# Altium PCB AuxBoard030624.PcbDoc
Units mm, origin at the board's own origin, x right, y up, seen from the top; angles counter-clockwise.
Board outline 193.93 x 90.42 mm, 2 copper layers (Top Layer, Bottom Layer); 177 components, 141 nets, 489 pads, 90 vias.
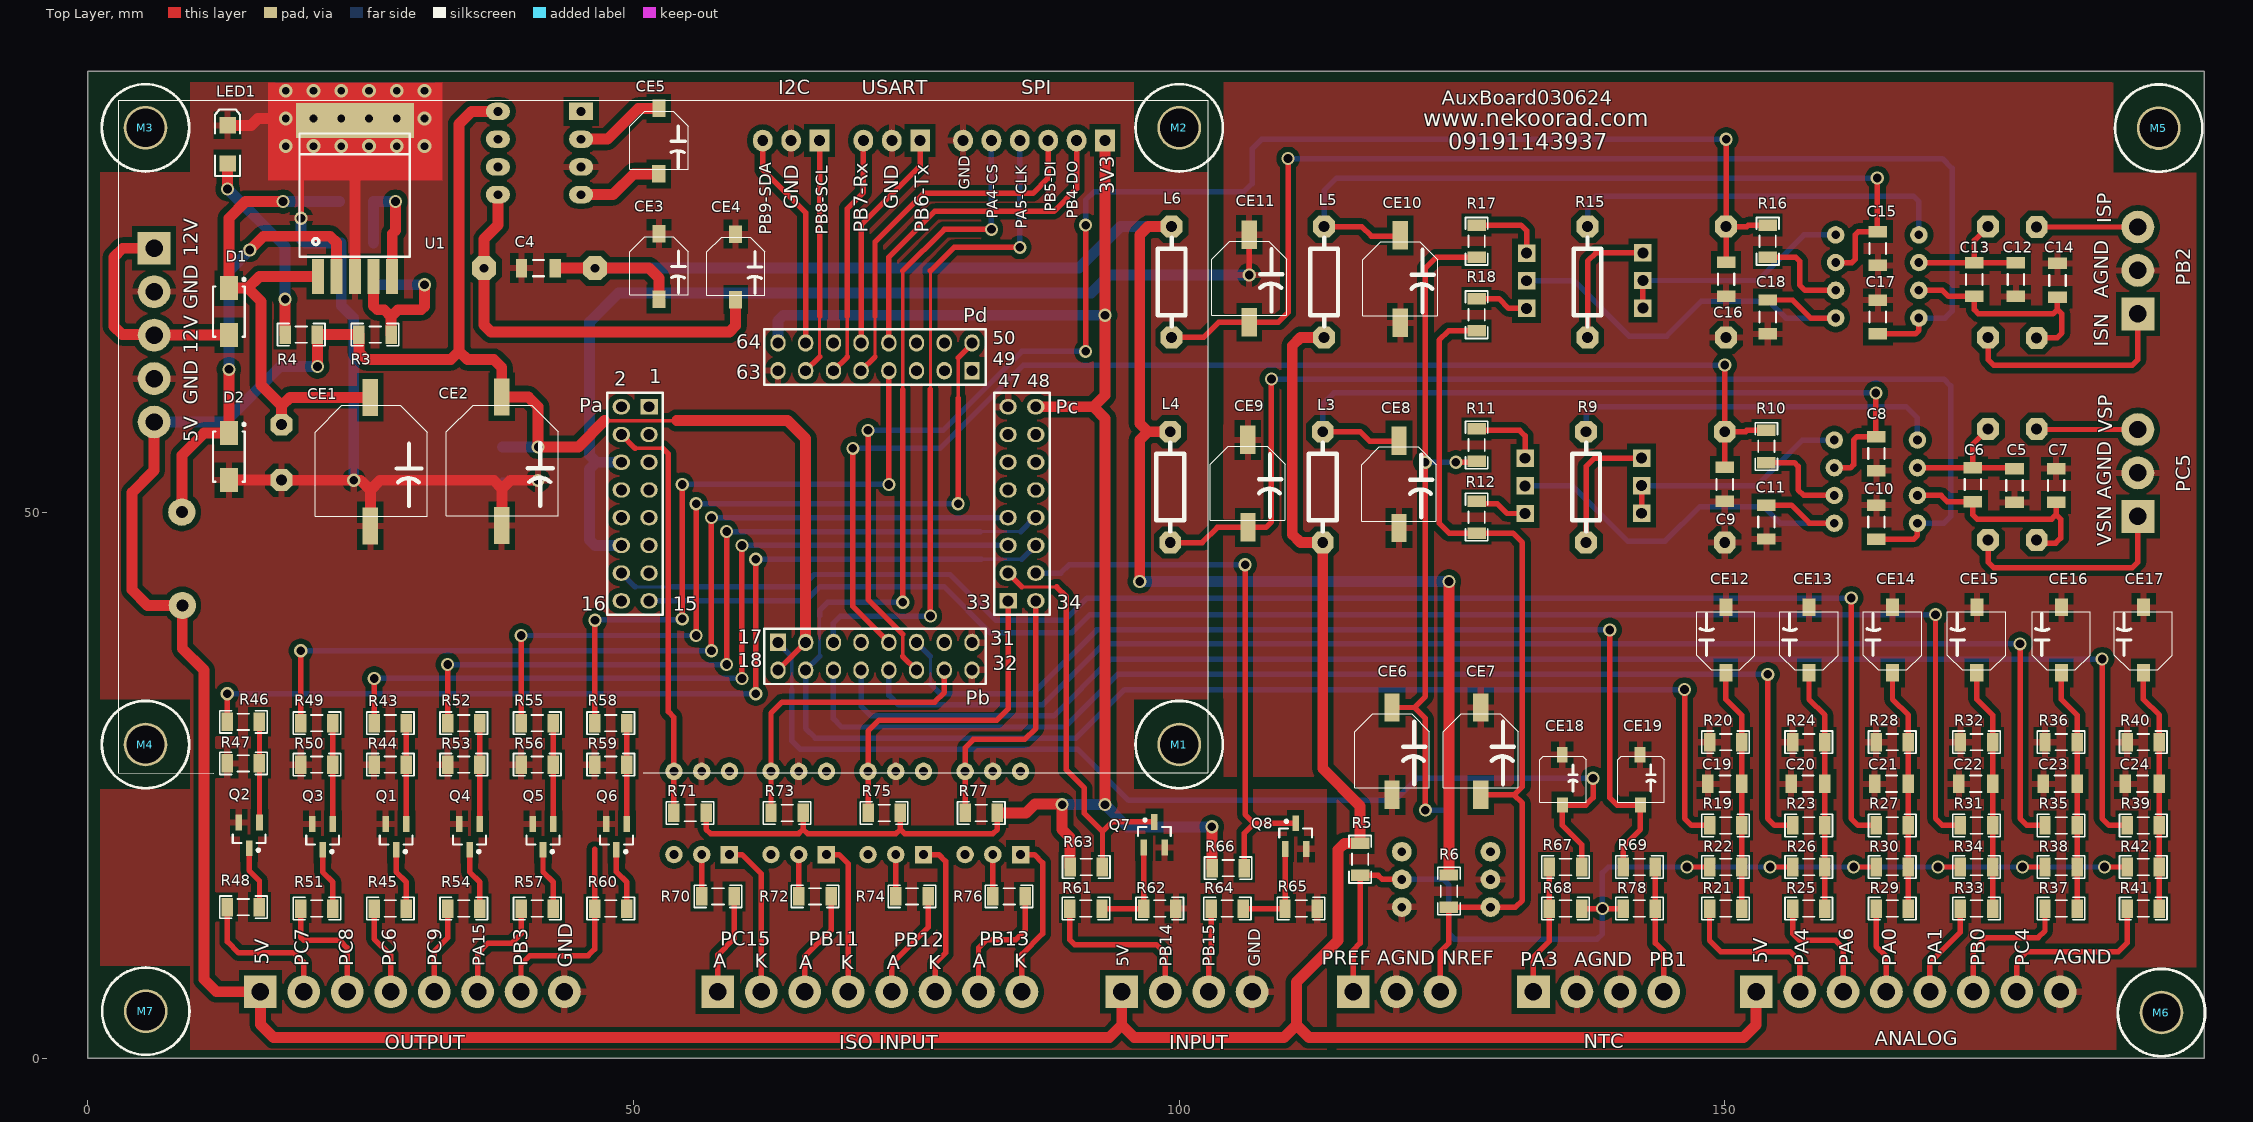
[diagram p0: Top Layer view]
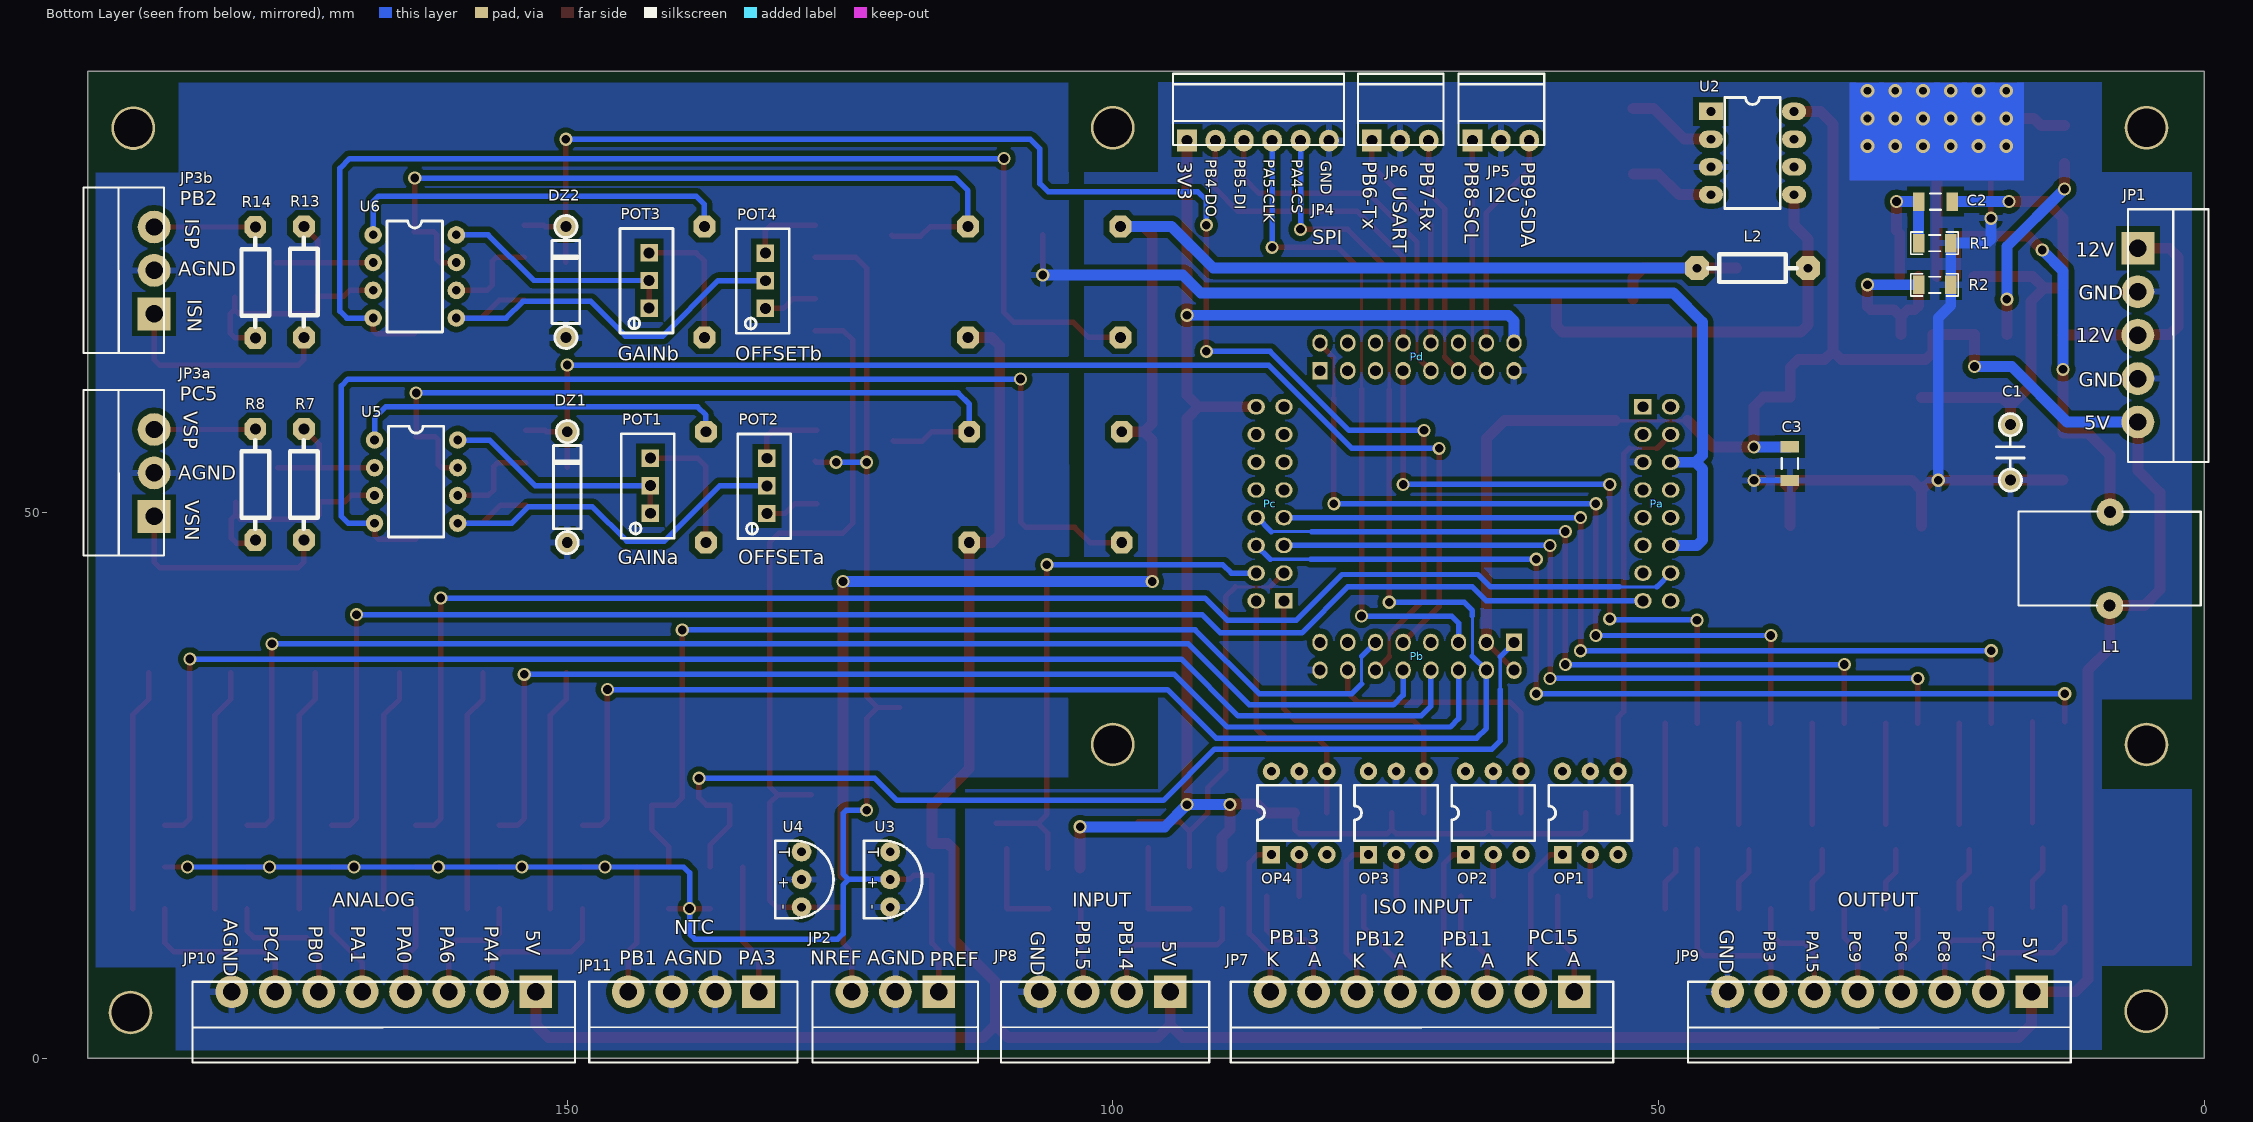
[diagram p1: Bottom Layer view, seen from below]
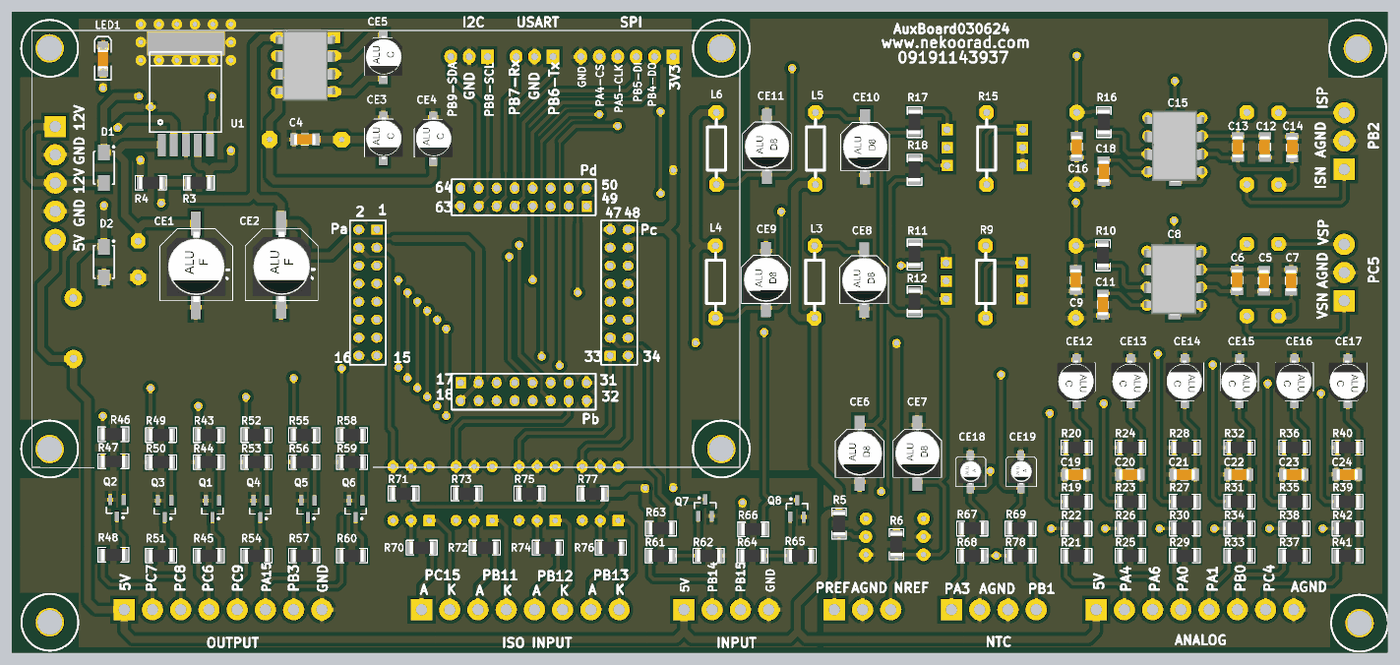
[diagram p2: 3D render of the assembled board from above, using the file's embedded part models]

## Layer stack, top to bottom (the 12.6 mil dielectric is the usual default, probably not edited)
Top Solder: solder mask 0.0102, Solder Resist, Dk 3.5
Top Layer: signal copper 0.0356
Dielectric 1: dielectric 0.32, FR-4, Dk 4.8
Bottom Layer: signal copper 0.0356
Bottom Solder: solder mask 0.0102, Solder Resist, Dk 3.5

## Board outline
0,0 0,90.424 193.929,90.424 193.929,0

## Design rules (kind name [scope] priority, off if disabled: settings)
Clearance Poly [All vs InPolygon] p1: gap=0.5 ignorepadtopadclearanceinfootprint=FALSE
Clearance [All] p2: gap=0.4 ignorepadtopadclearanceinfootprint=FALSE
PlaneClearance [All] p1: clearance=0.5
PlaneConnect [All] p1: planeconnectstyle=Relief reliefexpansion=0.508 reliefentries=4 reliefconductorwidth=0.6 reliefairgap=0.5
PolygonConnect [All] p1: connectstyle=Relief reliefconductorwidth=0.6 reliefentries=4 polygonreliefangle="90 Angle" airgapwidth=0.5
RoutingVias [All] p1: holewidth=0.711 width=1.27 viastyle="Through Hole" minholewidth=0.711 minwidth=1.27 maxholewidth=0.711 maxwidth=1.27
SolderMaskExpansion [All] p1: expansion=0.102 istentingtop=FALSE
Width [All] p1: maxlimit=1 minlimit=0.2 preferedwidth=0.5 minimp=50.000000 maximp=50.000000 favimp=50.000000
28 further rules are at their usual default settings.

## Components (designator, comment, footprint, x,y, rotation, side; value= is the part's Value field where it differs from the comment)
C1 "100N" C2P 17.78,58.048 r270 bottom
C2 "100N" SMD_CAP_1206. 24.642,78.486 r0 bottom
C3 "100N" SMD_CAP_1206. 37.973,54.483 r270 bottom
C4 "100N" SMD_CAP_1206. 41.3,72.39 r180 top
C5 "1N" SMD_CAP_1206. 176.53,52.476 r270 top
C6 "10N" SMD_CAP_1206. 172.72,52.553 r270 top
C7 "1N" SMD_CAP_1206. 180.34,52.476 r90 top
C8 "100N" SMD_CAP_1206. 163.883,55.396 r90 top
C9 "100N" SMD_CAP_1206. 149.987,52.578 r270 top
C10 "100N" SMD_CAP_1206. 163.883,49.122 r90 top
C11 "100N" SMD_CAP_1206. 153.797,49.124 r270 top
C12 "1N" SMD_CAP_1206. 176.657,71.349 r270 top
C13 "10N" SMD_CAP_1206. 172.847,71.349 r270 top
C14 "1N" SMD_CAP_1206. 180.467,71.272 r90 top
C15 "100N" SMD_CAP_1206. 164.01,74.192 r90 top
C16 "100N" SMD_CAP_1206. 150.114,71.374 r270 top
C17 "100N" SMD_CAP_1206. 164.01,67.918 r90 top
C18 "100N" SMD_CAP_1206. 153.924,67.92 r270 top
C19 "ND" SMD_CAP_1206. 149.991,25.146 r180 top
C20 "ND" SMD_CAP_1206. 157.611,25.146 r180 top
C21 "ND" SMD_CAP_1206. 165.26,25.146 r180 top
C22 "ND" SMD_CAP_1206. 172.978,25.146 r180 top
C23 "ND" SMD_CAP_1206. 180.725,25.146 r180 top
C24 "ND" SMD_CAP_1206. 188.247,25.146 r180 top
CE1 "470M/25" CAP-E-6 26.068,51.018 r0 top
CE2 "1000M/16" CAP-E-6 38.1,51.054 r0 top
CE3 "10M/25" CAP-E-3 52.414,70.651 r0 top
CE4 "10M/25" CAP-E-3 59.436,70.612 r0 top
CE5 "10M/25" CAP-E-3 52.399,82.126 r0 top
CE6 "47M" CAP-E-4 119.507,25.84 r0 top
CE7 "47M" CAP-E-4 127.635,25.84 r0 top
CE8 "47M" CAP-E-4 120.142,50.292 r0 top
CE9 "47M" CAP-E-4 106.299,50.351 r0 top
CE10 "47M" CAP-E-4 120.269,69.088 r0 top
CE11 "47M" CAP-E-4 106.426,69.147 r0 top
CE12 "ND" CAP-E-3 150.02,40.206 r180 top
CE13 "ND" CAP-E-3 157.64,40.206 r180 top
CE14 "ND" CAP-E-3 165.289,40.206 r180 top
CE15 "ND" CAP-E-3 173.007,40.206 r180 top
CE16 "ND" CAP-E-3 180.754,40.206 r180 top
CE17 "ND" CAP-E-3 188.276,40.206 r180 top
CE18 "1M" CAP-E-2 135.189,24.423 r0 top
CE19 "1M" CAP-E-2 142.33,24.423 r0 top
D1 "schottky" SMA-M 12.954,68.403 r270 top
D2 "schottky" SMA-M 12.954,55.118 r270 top
DZ1 "3V" D4P 149.987,47.244 r270 bottom
DZ2 "3V" D4P 150.114,66.04 r270 bottom
JP1 "DC_SUP" "dsip 5 right" 6.096,66.253 r180 bottom
JP2 "Ref" "dsip 3 right" 123.952,6.096 r270 bottom
JP3a "V/A Signal" "dsip 3 right" 187.833,57.658 r0 bottom
JP3b "V/A Signal" "dsip 3 right" 187.833,76.21 r0 bottom
JP4 "SPI" "SIP 6 Right" 93.204,84.074 r270 bottom
JP5 "I2C" "SIP 3 Right" 67.107,83.947 r270 bottom
JP6 "UART" "SIP 3 Right" 76.327,83.947 r270 bottom
JP7 "ISO DIN" "dsip 8 right" 57.763,6.071 r270 bottom
JP8 "DIN" "dsip 4 right" 102.727,6.096 r270 bottom
JP9 "DOUT" "dsip 8 right" 15.853,6.071 r270 bottom
JP10 "Analog" "dsip 8 right" 152.886,6.071 r270 bottom
JP11 "NTC" "dsip 4 right" 140.444,6.096 r270 bottom
L1 "100UH" INDUCTOR-ylw 0.401,49.893 r0 bottom
L2 "100UH" r4p#1 36.322,72.39 r270 bottom
L3 "100UH" r4p#2 113.157,47.244 r180 top
L4 "100UH" r4p#2 99.187,57.404 r0 top
L5 "100UH" r4p#2 113.284,66.04 r180 top
L6 "100UH" r4p#2 99.314,76.2 r0 top
LED1 "Red" LED_SMD_1206 15.048,83.815 r90 top
M1 "Comment" Stud-hole 100.006,28.745 r0 top locked value=DNP/MH
M2 "Comment" Stud-hole 100.006,85.245 r0 top locked value=DNP/MH
M3 "Comment" Stud-hole 5.306,85.245 r0 top locked value=DNP/MH
M4 "Comment" Stud-hole 5.306,28.745 r0 top locked value=DNP/MH
M5 "Comment" Stud-hole 189.738,85.217 r0 top value=DNP/MH
M6 "Comment" Stud-hole 189.992,4.191 r0 top value=DNP/MH
M7 "Comment" Stud-hole 5.334,4.318 r0 top value=DNP/MH
OP1 "4N28" DIP6 58.801,18.669 r90 bottom
OP2 "4N28" DIP6 67.691,18.669 r90 bottom
OP3 "4N28" DIP6 76.581,18.669 r90 bottom
OP4 "4N28" DIP6 85.471,18.669 r90 bottom
Pa "Header 8X2" HDR2X8#1 51.435,59.69 r270 bottom locked
Pb "Header 8X2" HDR2X8#2 63.246,38.1 r0 bottom locked
Pc "Header 8X2" HDR2X8#1 84.328,41.91 r90 bottom locked
Pd "Header 8X2" HDR2X8#1 81.026,62.992 r180 bottom locked
POT1 "ND" "pot multi turn" 142.367,49.931 r180 bottom
POT2 "ND" "pot multi turn" 131.699,49.911 r180 bottom
POT3 "ND" "pot multi turn" 142.494,68.727 r180 bottom
POT4 "ND" "pot multi turn" 131.826,68.707 r180 bottom
Q1 "2N2222" 2N2222 28.36,21.988 r180 top
Q2 "2N2222" 2N2222 14.898,22.115 r180 top
Q3 "2N2222" 2N2222 21.629,21.988 r180 top
Q4 "2N2222" 2N2222 35.091,21.988 r180 top
Q5 "2N2222" 2N2222 41.822,21.988 r180 top
Q6 "2N2222" 2N2222 48.553,21.988 r180 top
Q7 "2N2222" 2N2222 97.624,18.779 r0 top
Q8 "2N2222" 2N2222 110.578,18.652 r0 top
R1 "10K%" RES_1206 24.68,73.795 r180 bottom
R2 "2K2%" RES_1206 24.68,69.985 r180 bottom
R3 "47K%" RES_1206 26.374,65.413 r0 top
R4 "4K7%" RES_1206 19.542,67.175 r180 top
R5 "270R" RES_1206 117.467,18.275 r90 top
R6 "270R" RES_1206 125.595,15.354 r90 top
R7 "10K%" R4P 174.117,47.498 r0 bottom
R8 "10K%" R4P 178.562,57.658 r180 bottom
R9 "ND" R4P 137.287,57.404 r0 top
R10 "1K%" RES_1206 152.916,56.02 r270 top
R11 "ND" RES_1206 128.135,56.219 r90 top
R12 "ND" RES_1206 126.373,49.543 r270 top
R13 "10K%" R4P 174.117,66.04 r0 bottom
R14 "10K%" R4P 178.562,76.159 r180 bottom
R15 "ND" R4P 137.414,76.2 r0 top
R16 "1K%" RES_1206 153.043,74.816 r270 top
R17 "ND" RES_1206 128.135,74.888 r90 top
R18 "ND" RES_1206 126.373,68.085 r270 top
R19 "1K%" RES_1206 150.101,20.455 r0 top
R20 "ND" RES_1206 150.101,28.075 r0 top
R21 "ND" RES_1206 150.029,14.597 r180 top
R22 "ND" RES_1206 150.101,16.645 r0 top
R23 "1K%" RES_1206 157.721,20.455 r0 top
R24 "ND" RES_1206 157.721,28.075 r0 top
R25 "ND" RES_1206 157.649,14.597 r180 top
R26 "ND" RES_1206 157.721,16.645 r0 top
R27 "1K%" RES_1206 165.37,20.455 r0 top
R28 "ND" RES_1206 165.37,28.075 r0 top
R29 "ND" RES_1206 165.298,14.597 r180 top
R30 "ND" RES_1206 165.37,16.645 r0 top
R31 "1K%" RES_1206 173.088,20.455 r0 top
R32 "ND" RES_1206 173.088,28.075 r0 top
R33 "ND" RES_1206 173.016,14.597 r180 top
R34 "ND" RES_1206 173.088,16.645 r0 top
R35 "1K%" RES_1206 180.835,20.455 r0 top
R36 "ND" RES_1206 180.835,28.075 r0 top
R37 "ND" RES_1206 180.763,14.597 r180 top
R38 "ND" RES_1206 180.835,16.645 r0 top
R39 "1K%" RES_1206 188.357,20.455 r0 top
R40 "ND" RES_1206 188.357,28.075 r0 top
R41 "ND" RES_1206 188.285,14.597 r180 top
R42 "ND" RES_1206 188.357,16.645 r0 top
R43 "4K7" RES_1206 27.771,29.824 r0 top
R44 "2K2" RES_1206 27.699,27.776 r180 top
R45 "ND" RES_1206 27.699,14.597 r180 top
R46 "4K7" RES_1206 14.309,29.951 r0 top
R47 "2K2" RES_1206 14.237,27.903 r180 top
R48 "ND" RES_1206 14.237,14.724 r180 top
R49 "4K7" RES_1206 21.04,29.824 r0 top
R50 "2K2" RES_1206 20.968,27.776 r180 top
R51 "ND" RES_1206 20.968,14.597 r180 top
R52 "4K7" RES_1206 34.502,29.824 r0 top
R53 "2K2" RES_1206 34.43,27.776 r180 top
R54 "ND" RES_1206 34.43,14.597 r180 top
R55 "4K7" RES_1206 41.233,29.824 r0 top
R56 "2K2" RES_1206 41.161,27.776 r180 top
R57 "ND" RES_1206 41.161,14.597 r180 top
R58 "4K7" RES_1206 47.964,29.824 r0 top
R59 "2K2" RES_1206 47.892,27.776 r180 top
R60 "ND" RES_1206 47.892,14.597 r180 top
R61 "10K" RES_1206 91.496,12.835 r0 top
R62 "4K7" RES_1206 98.256,12.835 r0 top
R63 "10K" RES_1206 91.525,16.645 r0 top
R64 "10K" RES_1206 104.45,12.835 r0 top
R65 "4K7" RES_1206 111.21,12.835 r0 top
R66 "10K" RES_1206 104.529,16.532 r0 top
R67 "10K" RES_1206 135.438,16.645 r0 top
R68 "5K" RES_1206 135.366,14.597 r180 top
R69 "10K" RES_1206 142.126,18.407 r180 top
R70 "1K%" RES_1206 57.714,15.726 r180 top
R71 "10K%" RES_1206 55.232,21.598 r0 top
R72 "1K%" RES_1206 66.604,15.726 r180 top
R73 "10K%" RES_1206 64.122,21.598 r0 top
R74 "1K%" RES_1206 75.494,15.726 r180 top
R75 "10K%" RES_1206 73.012,21.598 r0 top
R76 "1K%" RES_1206 84.384,15.726 r180 top
R77 "10K%" RES_1206 81.902,21.598 r0 top
R78 "5K" RES_1206 142.198,12.835 r0 top
U1 "LM2576T-ADJ" D2PACK_TO263-5 24.511,76.327 r0 top
U2 "ICL7662" DIP8#1 45.212,86.741 r180 bottom
U3 "LM336-2V5" lm336 120.396,13.843 r180 bottom
U4 "LM336-2V5" lm336 128.524,13.843 r180 bottom
U5 "AD620" DIP8#2 167.64,56.642 r180 bottom
U6 "AD620" DIP8#2 167.767,75.438 r180 bottom

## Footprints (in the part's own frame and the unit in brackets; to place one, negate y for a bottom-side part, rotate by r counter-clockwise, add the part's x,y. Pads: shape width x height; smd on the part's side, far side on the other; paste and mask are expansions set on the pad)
2N2222 [mm] "SOT_23"
  rect 0.6x1.45 smd: 1(-0.85,0.525) 2(1.05,0.525) 3(0.1,2.875)
  silkscreen extent -1.4,1.6 1.6,3.17, body extent -1.4,1 1.6,2.4, height 1.1
C2P [mm]
  oct 2x2 hole 1: 1(0,0) 2(5.08,0)
  silkscreen extent -1.02,-1.27 6.1,1.27
CAP-E-2 [mm] "1u-50v"
  rect 1x1.4 smd: 1(-0.09,3.39) 2(-0.075,-1.22)
  silkscreen extent -2.17,-0.98 2.11,3.25, body extent -1.68,-0.65 1.62,2.95, height 5.4
CAP-E-3 [mm] "22u-35v"
  rect 1.2x1.6 smd: 1(-0.065,4.9) 2(-0.075,-1.1)
  silkscreen extent -2.72,-0.69 2.62,4.62, body extent -2.64,-1.03 2.66,4.87, height 5.41
CAP-E-4 [mm] "(100u-35v)(47u-16v)(220u-16v)(100u-16v)(10u-50v)"
  rect 1.4x2.6 smd: 1(-0.005,6.3) 2(0,-1.71)
  silkscreen extent -3.43,-1.07 3.43,5.71, body extent -3.27,-1.22 3.33,5.78, height 7.7
CAP-E-6 [mm] "(220u-35v)(470u-25v)"
  rect 1.4x3.4 smd: 1(-0.16,9.535) 2(-0.16,-2.25)
  silkscreen extent -5.22,-1.35 5.03,8.79, body extent -4.24,-1.54 4.06,8.36, height 10.2
D2PACK_TO263-5 [mm]
  rect 1.1x3.2 smd: 1(-3.4,-4.7) 2(-1.7,-4.7) 3(0,-4.7) 4(1.7,-4.7) 5(3.4,-4.7)
  rect 10.8x3.2 smd: 3(0,9.6)
  silkscreen extent -5.1,-2.9 5,8.4, body extent -5.1,-4.62 5.06,9.62, height 4.87
D4P [mm]
  oct 2x2 hole 1: 1(0,0) 2(-10.16,0)
  silkscreen extent -11.18,-1.27 1.02,1.27
DIP6 [mm]
  rect 1.6x1.6 hole 0.8: 1(0,0)
  round 1.6 hole 0.8: 2(0,-2.54) 3(0,-5.08) 4(7.62,-5.08) 5(7.62,-2.54) 6(7.62,0)
  silkscreen extent 1.27,-6.35 6.35,1.27
DIP8#1 [mm]
  rect 2.2x1.6 hole 0.8: 1(0,0)
  oval 2.2x1.6 hole 0.8: 2(0,-2.54) 3(0,-5.08) 4(0,-7.62) 5(7.62,-7.62) 6(7.62,-5.08) 7(7.62,-2.54) 8(7.62,0)
  silkscreen extent 1.27,-8.89 6.35,1.27, body extent -1.42,-8.88 9.14,1.02, height 3.75
DIP8#2 [mm]
  round 1.6 hole 0.8: 1(0,0) 2(0,-2.54) 3(0,-5.08) 4(0,-7.62) 5(7.62,-7.62) 6(7.62,-5.08) 7(7.62,-2.54) 8(7.62,0)
  silkscreen extent 1.27,-8.89 6.35,1.27, body extent -1.42,-8.88 9.14,1.02, height 3.75
"dsip 3 right" [mm]
  rect 3x3 hole 1.6: 1(0,8.011)
  round 3 hole 1.6: 2(0,4.031) 3(0,0.051)
  silkscreen extent -0.91,-3.56 6.48,11.59
"dsip 4 right" [mm]
  rect 3x3 hole 1.6: 1(0,7.985)
  round 3 hole 1.6: 2(0,4.005) 3(0,0.025) 4(0,-3.955)
  silkscreen extent -0.91,-7.52 6.48,11.56
"dsip 5 right" [mm]
  rect 3x3 hole 1.6: 1(0,7.96)
  round 3 hole 1.6: 2(0,3.98) 3(0,0) 4(0,-3.98) 5(0,-7.96)
  silkscreen extent -0.91,-11.63 6.48,11.53
"dsip 8 right" [mm]
  rect 3x3 hole 1.6: 1(-0.025,0.025)
  round 3 hole 1.6: 2(-0.025,-3.955) 3(-0.025,-7.935) 4(-0.025,-11.915) 5(-0.025,-15.895) 6(-0.025,-19.875) 7(-0.025,-23.855) 8(-0.025,-27.835)
  silkscreen extent -0.94,-31.45 6.45,3.6
HDR2X8#1 [mm] "Connector; Header; 8x2 Position"
  rect 1.4x1.6 hole 1: 1(0,0)
  oval 1.4x1.6 hole 1: 2(0,2.54) 3(2.54,0) 4(2.54,2.54) 5(5.08,0) 6(5.08,2.54) 7(7.62,0) 8(7.62,2.54) 9(10.16,0) 10(10.16,2.54) 11(12.7,0) 12(12.7,2.54) 13(15.24,0) 14(15.24,2.54) 15(17.78,0) 16(17.78,2.54)
HDR2X8#2 [mm] "Connector; Header; 8x2 Position"
  rect 1.5x1.6 hole 1: 1(0,0)
  oval 1.4x1.6 hole 1: 2(0,2.54) 3(2.54,0) 4(2.54,2.54) 5(5.08,0) 6(5.08,2.54) 7(7.62,0) 8(7.62,2.54) 9(10.16,0) 10(10.16,2.54) 11(12.7,0) 12(12.7,2.54) 13(15.24,0) 14(15.24,2.54) 15(17.78,0) 16(17.78,2.54)
INDUCTOR-ylw [mm]
  round 2.5 hole 1.1: 1(8.275,8.405) 2(8.235,-0.145)
  silkscreen extent -0.07,-0.21 16.63,8.42
LED_SMD_1206 [mm] "SMD"
  rect 1.5x1.5 smd: 1(-1.844,2.221) 2(1.656,2.221)
  silkscreen extent -2.99,1.07 3.11,3.37, body extent -1.74,1.46 1.56,2.91, height 1.36
lm336 [mm]
  round 1.8 hole 0.8: 1(0,0) 2(0,2.54) 3(0,5.08)
  silkscreen extent -2.41,-1.02 2.92,6.1
"pot multi turn" [mm]
  rect 1.6x1.6 hole 1: 1(0,5.06) 2(0,0) 3(0,2.53)
  silkscreen extent -2.67,-2.29 2.18,7.29
r4p#1 [mm]
  oct 2.2x2.2 hole 0.8: 1(0,0) 2(0,-10.16)
  silkscreen extent -1.27,-9.14 1.27,-1.02
r4p#2 [mm]
  oct 2x2 hole 1: 1(0,0) 2(0,-10.16)
  silkscreen extent -1.27,-9.14 1.27,-1.02
R4P [mm]
  oct 2x2 hole 1: 1(0,0) 2(0,-10.16)
  silkscreen extent -1.27,-9.14 1.27,-1.02
RES_1206 [mm] "SMD"
  rect 1.05x1.7 smd: 1(-1.511,0.881) 2(1.439,0.881)
  silkscreen extent -2.21,-0.14 2.14,1.91, body extent -1.69,0.03 1.61,1.73, height 0.94
"SIP 3 Right" [mm]
  rect 2x1.8 hole 1: 1(-0.127,0.051)
  oval 2x1.8 hole 1: 2(-0.127,2.651) 3(-0.127,5.251)
  silkscreen extent -6.25,-1.22 0.28,6.63
"SIP 6 Right" [mm]
  rect 2x1.8 hole 1: 1(0,0)
  oval 2x1.8 hole 1: 2(0,2.6) 3(0,5.2) 4(0,7.8) 5(0,10.4) 6(0,13)
  silkscreen extent -6.12,-1.3 0.41,14.38
SMA-M [mm] "Molded Diode, 2-Leads, Body 4.30x2.70mm, IPC Low Density"
  rect 2.2x1.65 smd: 1(2.15,0) 2(-2.15,0)
  silkscreen extent -3.07,-1.45 2.3,1.5, body extent -2.3,-1.45 2.3,1.45, height 2.44
SMD_CAP_1206. [mm]
  rect 1.05x1.7 smd: 1(-1.549,0) 2(1.549,0)
  silkscreen extent -0.5,-0.75 0.5,0.75, body extent -1.52,-0.77 1.53,0.75, height 0.75
Stud-hole [mm]
  round 4 hole 3.5: 1(0,0)
  silkscreen extent -4,-4 4,4

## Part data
C1 C2 C3 C4 C5 C6 C7 C8 C9 C10 C11 C12 C13 C14 C15 C16 C17 C18 C19 C20 C21 C22 C23 C24: library part C
CE1 CE2 CE3 CE4 CE5 CE6 CE7 CE8 CE9 CE10 CE11 CE12 CE13 CE14 CE15 CE16 CE17 CE18 CE19: library part E
D1 D2: library part Diode, "Default Diode"
DZ1 DZ2: library part Z
JP1: library part "HEADER 5"
JP2 JP3a JP3b JP5 JP6: library part "Header 3", "Header, 3-Pin"
JP4: library part "HEADER 6"
JP7 JP9 JP10: library part "HEADER 8"
JP8 JP11: library part "Header 4", "Header, 4-Pin"
L1 L2 L3 L4 L5 L6: library part "INDUCTOR IRON"
LED1: library part LED, "LED"
M1 M2 M3 M4 M5 M6 M7: library part SCMH_M1P6, "SCREW mouting, M1.6, 1.6mm diameter and 3.2mm PanHead"
OP1 OP2 OP3 OP4: library part OPTODIP6
Pa Pb Pc Pd: "Header, 8-Pin, Dual row"
POT1 POT2 POT3 POT4: library part POT2
Q1 Q2 Q3 Q4 Q5 Q6 Q7 Q8: library part 1FW, "NPN"
R1 R2 R3 R4 R5 R6 R7 R8 R9 R10 R11 R12 R13 R14 R15 R16 R17 R18 R19 R20 R21 R22 R23 R24 R25 R26 R27 R28 R29 R30 R31 R32 R33 R34 R35 R36 R37 R38 R39 R40 R41 R42 R43 R44 R45 R46 R47 R48 R49 R50 R51 R52 R53 R54 R55 R56 R57 R58 R59 R60 R61 R62 R63 R64 R65 R66 R67 R68 R69 R70 R71 R72 R73 R74 R75 R76 R77 R78: library part R
U1: library part LM2576
U3 U4: library part LM336

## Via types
v1: diameter 1.2, hole 0.8, Top Layer to Bottom Layer, 72 vias
v2: diameter 1.27, hole 0.711, Top Layer to Bottom Layer, 18 vias

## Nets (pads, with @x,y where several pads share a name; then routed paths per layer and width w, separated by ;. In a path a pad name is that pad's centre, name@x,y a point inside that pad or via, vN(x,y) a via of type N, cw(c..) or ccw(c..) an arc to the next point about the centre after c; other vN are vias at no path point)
3V3: JP4.1 Pc.16 Pd.16 R63.1 R66.1 R71.2 R73.2 R75.2 R77.2 | length 163.6
  Top Layer w0.5: R71.2 56.671,20.984 57.081,20.574 65.151,20.574 65.561,20.984 ; R73.2 65.561,20.984 ; R75.2 74.451,20.984 ; R77.2 83.341,20.984 82.931,20.574 74.861,20.574 74.451,20.984 ; v1@89.232,23.29 v1(89.281,23.241) ; v1(102.997,21.209) v1@103.008,21.198 ; R66.1@103.008,17.424 R66.1 ; 65.561,20.984 65.971,20.574 74.041,20.574 74.451,20.984
  Top Layer w1: R77.2 85.979,22.479 86.79,23.29 v1@89.232,23.29 ; Pc.16 92.149,59.69 ; v1(89.281,23.241) 89.281,20.955 90.014,20.222 R63.1 ; JP4.1 93.204,60.745 92.149,59.69 ; v1(93.218,23.241) 93.218,58.621 92.149,59.69 ; R66.1@103.008,17.424 v1@103.008,21.198
  Bottom Layer w1: Pd.16 63.246,67.564 63.754,68.072 v1(93.218,68.072) ; v1(89.281,23.241) v1(93.218,23.241) 95.25,21.209 v1(102.997,21.209)
5VN: C4.1 CE3.2 L2.2 L4.1 L6.1 R6.2 | length 159.1
  Top Layer w1: C4.1 L2.2 51.435,72.39 52.339,71.486 CE3.2 ; v1(96.393,43.688) 96.393,56.642 97.155,57.404 ; L4.1 97.155,57.404 ; L6.1 97.155,76.2 96.393,75.438 96.393,58.166 97.155,57.404 ; R6.2 v1(124.714,43.688)
  Bottom Layer w1: L2.2 90.805,72.39 94.615,76.2 L6.1 ; v1(96.393,43.688) v1(124.714,43.688)
5VP: C3.1 CE2.1 JP1.5 JP8.1 JP9.1 JP10.1 L1.1 L3.1 L5.1 Pb.2 Pb.3 R3.1 R4.1 R5.2 U2.8 | length 410.2
  Top Layer w0.3: 47.371,58.42 53.975,58.42
  Top Layer w0.5: Pb.2 Pb.3
  Top Layer w1: JP1.5 6.096,53.848 4.064,51.816 4.064,42.926 5.502,41.488 L1.1 8.676,37.552 10.668,35.56 10.668,7.239 11.811,6.096 JP9.1 15.828,3.095 17.018,1.905 93.599,1.905 94.742,3.048 ; v1(21.053,63.373) R4.1 R3.1 24.863,64.672 25.527,64.008 33.274,64.008 34.036,64.77 ; U2.8 35.179,86.741 34.036,85.598 34.036,64.77 ; 47.371,58.42 44.958,56.007 v1(41.275,56.007) 41.275,59.69 40.376,60.589 CE2.1 37.94,63.279 37.211,64.008 34.798,64.008 34.036,64.77 ; 53.975,58.42 64.135,58.42 65.786,56.769 Pb.3 ; JP8.1 94.742,3.048 ; L5.1 111.125,66.04 110.363,65.278 110.363,48.006 111.125,47.244 L3.1 113.157,26.543 116.586,23.114 R5.2 116.561,19.689 115.14,19.689 114.554,19.103 114.554,10.795 110.744,6.985 110.744,3.048 ; JP10.1 152.861,3.048 151.718,1.905 111.887,1.905 110.744,3.048 ; 94.742,3.048 95.885,1.905 109.601,1.905 110.744,3.048
  Bottom Layer w0.5: C3.1@37.973,55.905 C3.1@37.998,55.88
  Bottom Layer w1: JP1.5@6.223,58.42 JP1.5 12.573,58.293 17.653,63.373 v1(21.053,63.373) ; C3.1@37.998,56.007 v1(41.275,56.007)
11V: C1.1 C2.1 CE1.1 D1.2 U1.1 | length 48
  Top Layer w1: C1.1 17.78,59.791 ; v1(17.907,78.486) 14.478,78.486 12.954,76.962 D1.2 14.673,70.553 ; U1.1 15.747,71.627 14.673,70.553 ; CE1.1 18.542,60.553 17.78,59.791 ; 14.673,70.553 15.875,69.351 15.875,61.696 17.78,59.791
  Bottom Layer w1: v1(17.907,78.486) C2.1
12V: D1.1 JP1.1 JP1.3 | length 21.2
  Top Layer w1: JP1.1 3.22,74.213 2.413,73.406 2.413,67.056 3.175,66.294 6.055,66.294 JP1.3 D1.1
+INa: C6.2 C7.1 R8.2 U5.3 | length 20.4
  Top Layer w0.5: U5.3 169.799,51.562 170.358,51.003 C6.2 172.72,49.784 173.101,49.403 179.93,49.403 180.34,49.813 ; R8.2@178.435,47.203 180.299,47.203 180.75,47.654 180.75,49.403 180.34,49.813 ; C7.1 180.34,49.813
+INb: C13.2 C14.1 R14.2 U6.3 | length 20.4
  Top Layer w0.5: U6.3 169.926,70.358 170.485,69.799 C13.2 172.847,68.58 173.228,68.199 180.057,68.199 180.467,68.609 ; R14.2 180.426,65.999 180.877,66.45 180.877,68.199 180.467,68.609 ; C14.1 180.467,68.609
+VSa: C8.2 CE8.1 L3.2 U5.7 | length 71.4
  Top Layer w0.5: L3.2 116.586,57.404 117.475,56.515 120.06,56.515 CE8.1 ; U5.7 161.505,54.102 161.798,54.395 161.798,56.642 162.101,56.945 C8.2 163.83,56.998 v1(163.83,60.96)
  Bottom Layer w0.5: L3.2 113.157,59.944 114.173,60.96 v1(163.83,60.96)
+VSb: C15.2 CE10.1 L5.2 U6.7 | length 73.1
  Top Layer w0.5: L5.2 116.713,76.2 117.602,75.311 120.187,75.311 CE10.1 ; U6.7 161.632,72.898 161.925,73.191 161.925,75.438 162.228,75.741 C15.2 163.957,75.794 v1(163.957,80.645)
  Bottom Layer w0.5: L5.2 113.285,79.503 114.427,80.645 v1(163.957,80.645)
-INa: C5.1 C6.1 R7.2 U5.2 | length 13
  Top Layer w0.5: U5.2 C6.1 ; R7.2 172.72,56.261 C6.1 ; C5.1@176.53,54.102 C6.1
-INb: C12.1 C13.1 R13.2 U6.2 | length 12.7
  Top Layer w0.5: U6.2 C13.1 ; R13.2 172.847,74.93 C13.1 ; C12.1 C13.1
-VSa: C10.1 CE9.2 L4.2 U5.4 | length 105.9
  Top Layer w0.5: L4.2 102.108,47.244 103.505,48.641 CE9.2 107.95,48.641 108.458,49.149 v1(108.458,62.23) ; C10.1 167.311,47.573 167.64,47.901 U5.4
  Bottom Layer w0.5: v1(108.458,62.23) 170.053,62.23 170.688,61.595 170.688,49.657 170.053,49.022 U5.4
-VSb: C17.1 CE11.2 L6.2 U6.4 | length 108.3
  Top Layer w0.5: L6.2 102.235,66.04 103.632,67.437 CE11.2 109.093,67.437 109.982,68.326 v1(109.982,82.423) ; C17.1 167.438,66.369 167.767,66.697 U6.4
  Bottom Layer w0.5: v1(109.982,82.423) 169.926,82.423 170.815,81.534 170.815,68.453 170.18,67.818 U6.4
ADC1-EXTI15: OP1.4 Pa.4 R71.1 | length 38.2
  Top Layer w0.3: 50.165,55.88 52.705,55.88
  Top Layer w0.5: Pa.4 50.165,55.88 ; 52.705,55.88 53.213,55.372 53.213,31.75 53.721,31.242 OP1.4 R71.1
ADC1-IN1: Pa.14 R27.1 | length 139
  Top Layer w0.5: v1(161.573,42.164) 161.573,21.971 162.208,21.336 R27.1
  Bottom Layer w0.3: 50.165,43.18 53.594,43.18
  Bottom Layer w0.5: Pa.14 50.165,43.18 ; 53.594,43.18 65.405,43.18 66.548,44.323 78.994,44.323 83.185,40.132 89.535,40.132 91.567,42.164 v1@161.544,42.164
ADC1-IN2: Pa.15 R31.1 | length 142
  Top Layer w0.5: v1(169.291,40.64) 169.291,21.971 169.926,21.336 R31.1
  Bottom Layer w0.5: Pa.15 65.786,41.91 67.056,43.18 78.486,43.18 82.688,38.978 90.159,38.978 91.821,40.64 v1(169.291,40.64)
ADC1-IN4: CE18.2 Pb.1 R67.2 | length 97.3
  Top Layer w0.5: R67.2 136.877,19.587 135.114,21.35 CE18.2 137.249,23.203 137.922,23.876 v1(137.922,25.654)
  Bottom Layer w0.3: 64.516,33.782 64.516,36.78
  Bottom Layer w0.5: Pb.1@63.246,38.05 64.516,36.78 ; 64.516,33.782 64.516,29.083 65.278,28.321 90.678,28.321 95.377,23.622 119.761,23.622 121.793,25.654 v1(137.922,25.654)
ADC1-IN11: Pb.10 R35.1 | length 127.2
  Top Layer w0.5: v1(177.038,37.973) 177.038,21.971 177.673,21.336 R35.1
  Bottom Layer w0.5: Pb.10 73.406,33.274 74.295,32.385 87.503,32.385 93.091,37.973 v1(177.038,37.973)
ADC1-IN12: CE19.2 Pb.11 R69.2 | length 94.1
  Top Layer w0.5: v1(139.447,39.243) 139.447,23.876 140.12,23.203 CE19.2 142.255,20.97 140.687,19.402 R69.2
  Bottom Layer w0.3: 77.216,34.29 77.216,36.83
  Bottom Layer w0.5: Pb.11 77.216,36.83 ; 77.216,34.29 78.105,33.401 86.614,33.401 92.456,39.243 v1(139.447,39.243)
ADC2-EXTI11: OP2.4 Pb.14 R73.1 | length 27.8
  Top Layer w0.5: R73.1 OP2.4 62.611,31.623 63.627,32.639 77.597,32.639 78.486,33.528 Pb.14
ADC2-IN5: Pb.8 R39.1 | length 136.7
  Top Layer w0.5: v1(184.56,36.576) 184.56,21.971 185.195,21.336 R39.1
  Bottom Layer w0.5: Pb.8 70.866,32.258 71.755,31.369 88.519,31.369 93.726,36.576 v1(184.56,36.576)
ADC2-IN11: C9.1 DZ1.2 Pb.9 R10.1 | length 115.4
  Top Layer w0.5: v1(70.104,55.88) 70.104,41.402 Pb.9 ; C9.1 DZ1.2 ; v1@149.987,63.5 DZ1.2 ; R10.1 152.019,57.531 151.892,57.404 DZ1.2
  Bottom Layer w0.5: v1(70.104,55.88) 78.105,55.88 85.736,63.511 v1(149.987,63.511)
ADC2-IN12: C16.1 DZ2.2 Pb.12 R16.1 | length 138.6
  Top Layer w0.3: 74.676,36.83 74.676,38.862
  Top Layer w0.5: v1(71.501,57.531) 71.501,42.037 74.676,38.862 ; 74.676,36.83 Pb.12 ; v1(91.44,64.77) v1(91.44,76.327) ; C16.1 DZ2.2 ; v1(150.114,84.201) DZ2.2 ; R16.1 152.146,76.327 152.019,76.2 DZ2.2
  Bottom Layer w0.5: v1(71.501,57.531) 78.359,57.531 85.598,64.77 v1(91.44,64.77) ; v1(91.44,76.327) 91.44,78.613 92.202,79.375 105.918,79.375 106.68,80.137 106.68,83.312 107.569,84.201 v1(150.114,84.201)
AGND: C5.2 C7.2 C8.1 C9.2 C10.2 C11.2 C12.2 C14.2 C15.1 C16.2 C17.2 C18.2 C19.2 C20.2 C21.2 C22.2 C23.2 C24.2 CE6.2 CE7.1 CE8.2 CE9.1 CE10.2 CE11.1 CE12.2 CE13.2 CE14.2 CE15.2 CE16.2 CE17.2 CE18.1 CE19.1 DZ1.1 DZ2.1 JP2.2 JP3a.2 JP3b.2 JP10.8 JP11.2 JP11.3 Pa.6 Pa.12 R20.1 R24.1 R28.1 R32.1 R36.1 R40.1 U3.1 U4.2 | length 91.8
  Top Layer w0.5: v1(106.421,71.755) CE11.1
  Bottom Layer w1: Pa.12 46.482,46.99 45.974,47.498 45.974,53.975 46.609,54.61 ; Pa.6 46.609,54.61 ; v1@106.426,71.755 93.599,71.755 91.948,70.104 48.641,70.104 45.974,67.437 45.974,55.245 46.609,54.61
AIO1: JP10.2 R21.2 | length 14.8
  Top Layer w0.5: R21.2 148.59,10.795 149.606,9.779 155.956,9.779 156.841,8.894 JP10.2
AIO2: JP10.3 R25.2 | length 11.5
  Top Layer w0.5: R25.2 156.21,11.43 156.845,10.795 160.147,10.795 160.821,10.121 JP10.3
AIO3: JP10.4 R29.2 | length 8
  Top Layer w0.5: R29.2 163.859,10.258 164.801,9.316 JP10.4
AIO4: JP10.5 R33.2 | length 8.8
  Top Layer w0.5: JP10.5 168.781,8.761 171.577,11.557 R33.2
AIO5: JP10.6 R37.2 | length 13.2
  Top Layer w0.5: JP10.6 172.761,9.947 173.863,11.049 178.689,11.049 179.324,11.684 R37.2
AIO6: JP10.7 R41.2 | length 16.7
  Top Layer w0.5: JP10.7 176.741,8.847 177.673,9.779 186.055,9.779 186.846,10.57 R41.2
BKL: Pa.2
Buzzer: Pb.13
DAC1-OUT1: JP4.5 Pb.4 R19.1 | length 164.5
  Top Layer w0.3: 74.676,61.245 74.676,72.136
  Top Layer w0.5: v1(74.676,41.783) 74.676,61.245 ; 74.676,72.136 78.486,75.946 v1(82.804,75.946) ; v1(146.304,33.782) 146.304,21.971 146.939,21.336 R19.1
  Bottom Layer w0.3: 67.056,36.83 67.056,40.54
  Bottom Layer w0.5: 67.056,36.83 Pb.4 65.786,30.226 66.675,29.337 90.551,29.337 94.996,33.782 v1(146.304,33.782) ; 67.056,40.54 67.056,41.021 67.818,41.783 v1(74.676,41.783) ; v1(82.804,75.946) JP4.5
DAC2-OUT1: Pb.6 R23.1 | length 108.1
  Top Layer w0.5: v1(153.924,35.179) 153.924,21.971 154.559,21.336 R23.1
  Bottom Layer w0.5: Pb.6 68.326,31.115 69.088,30.353 89.535,30.353 94.361,35.179 v1(153.924,35.179)
EN: Pa.16
GND: C1.2 C3.2 C4.2 CE1.2 CE2.2 CE3.1 CE4.1 D2.1 JP1.2 JP1.4 JP4.6 JP5.2 JP6.2 JP8.4 JP9.8 LED1.2 OP1.5 OP2.5 OP3.5 OP4.5 Pa.5 Pb.15 Pb.16 Pc.15 Pd.15 Q1.2 Q2.2 Q3.2 Q4.2 Q5.2 Q6.2 Q7.2 Q8.2 R1.2 R2.2 R44.2 R47.2 R50.2 R53.2 R56.2 R59.2 R62.2 R65.2 U1.3 U2.3 | length 94.6
  Top Layer w0.5: v1(19.558,76.962) 19.558,82.423 v2(20.701,83.566)
  Top Layer w1: LED1.2 14.986,85.471 15.621,86.106 v2(18.161,86.106) ; D2.1 C1.2 ; C1.2@17.78,52.959 v1(24.384,52.959) 25.019,52.959 25.908,52.07 ; U1.3@24.511,71.627 U1.3@24.511,85.927 ; CE1.2 25.908,52.07 ; CE2.2 37.973,48.837 37.973,52.197 ; v1@41.275,52.959 38.735,52.959 37.973,52.197 ; 25.908,52.07 26.797,52.959 37.211,52.959 37.973,52.197
  Bottom Layer w0.5: C3.2@37.973,52.807 C3.2@37.986,52.819 ; C3.2@37.986,52.946 v1(41.262,52.946)
  Bottom Layer w1: v1(19.558,76.962) 19.558,75.057 19.939,74.676 R1.2 R2.2 23.241,68.961 24.384,67.818 v1(24.384,52.959)
  other v2: 18.161,83.566 23.241,83.566 25.781,83.566 28.321,83.566 30.861,83.566 20.701,86.106 23.241,86.106 25.781,86.106 28.321,86.106 30.861,86.106 18.161,88.646 20.701,88.646 23.241,88.646 25.781,88.646 28.321,88.646 30.861,88.646
I2C1-SCL: JP5.1 Pd.13 | length 21.6
  Top Layer w0.3: 67.056,64.262 67.056,67.972
  Top Layer w0.5: Pd.13 67.056,64.262 ; 67.056,67.972 JP5.1
I2C1-SDA: JP5.3 Pd.14 | length 20.2
  Top Layer w0.5: JP5.3 61.856,81.4 65.786,77.47 Pd.14
ISN: JP3b.1 R13.1 | length 20.4
  Top Layer w0.5: R13.1 174.117,64.008 174.625,63.5 187.325,63.5 187.833,64.008 JP3b.1
ISP: JP3b.3 R14.1 | length 9.3
  Top Layer w0.5: R14.1 JP3b.3
K-R-A: Pc.9
K-R-B: Pc.10
KEY3-R: Pc.11
KEY4: Pc.12
KEY5: Pc.13
KEY6: Pa.3
LCD-D4: Pa.8
LCD-D5: Pa.9
LCD-D6: Pa.10
LCD-D7: Pa.11
LED1: Pd.3
LED2: Pd.4
LED3: Pd.5
LED4: Pd.6
NetC2_2: C2.2 R1.1 U1.5 | length 12.8
  Top Layer w1: U1.5 27.911,75.536 28.201,75.826 v1(28.201,78.486)
  Bottom Layer w1: R1.1 C2.2 v1(28.201,78.486)
NetC19_1: C19.1 CE12.1 R19.2 R20.2 R21.1 R22.2 | length 22.2
  Top Layer w0.5: CE12.1 150.085,32.893 151.54,31.438 R20.2 C19.1 R19.2 R22.2 R21.1
NetC20_1: C20.1 CE13.1 R23.2 R24.2 R25.1 R26.2 | length 22.2
  Top Layer w0.5: CE13.1 157.705,32.893 159.16,31.438 R24.2 C20.1 R23.2 R26.2 R25.1
NetC21_1: C21.1 CE14.1 R27.2 R28.2 R29.1 R30.2 | length 22.2
  Top Layer w0.5: CE14.1 165.354,32.893 166.809,31.438 R28.2 C21.1 R27.2 R30.2 R29.1
NetC22_1: C22.1 CE15.1 R31.2 R32.2 R33.1 R34.2 | length 22.2
  Top Layer w0.5: CE15.1 173.072,32.893 174.527,31.438 R32.2 C22.1 R31.2 R34.2 R33.1
NetC23_1: C23.1 CE16.1 R35.2 R36.2 R37.1 R38.2 | length 22.2
  Top Layer w0.5: CE16.1 180.819,32.893 182.274,31.438 R36.2 C23.1 R35.2 R38.2 R37.1
NetC24_1: C24.1 CE17.1 R39.2 R40.2 R41.1 R42.2 | length 22.2
  Top Layer w0.5: CE17.1 188.341,32.893 189.796,31.438 R40.2 C24.1 R39.2 R42.2 R41.1
NetCE4_2: CE4.2 L2.1 U2.5 | length 38.4
  Top Layer w1: U2.5 37.592,76.327 36.322,75.057 L2.1 36.322,67.183 36.957,66.548 58.801,66.548 59.361,67.108 CE4.2
NetCE5_1: CE5.1 U2.2 | length 8.3
  Top Layer w1: U2.2 47.625,84.201 50.45,87.026 CE5.1
NetCE5_2: CE5.2 U2.4 | length 7.9
  Top Layer w1: U2.4 48.133,79.121 50.038,81.026 CE5.2
NetD2_2: D2.2 L1.2 U1.2 | length 39.7
  Top Layer w1: L1.2 8.636,55.245 10.659,57.268 D2.2 v1(12.954,63.119) ; v1(14.859,74.041) 16.129,75.311 22.225,75.311 22.811,74.725 U1.2
  Bottom Layer w1: v1(12.954,63.119) 12.954,72.136 v1(14.859,74.041)
NetLED1_1: LED1.1 R4.2 | length 17.9
  Top Layer w1: v1(12.827,79.629) LED1.1 ; R4.2 v1(18.103,69.538)
  Bottom Layer w1: v1(12.827,79.629) 18.103,74.353 v1(18.103,69.538)
NetOP1_2: OP1.2 R70.2 | length 3.8
  Top Layer w0.5: R70.2 OP1.2@56.275,18.655
NetOP2_2: OP2.2 R72.2 | length 3.8
  Top Layer w0.5: R72.2 OP2.2@65.165,18.655
NetOP3_2: OP3.2 R74.2 | length 3.8
  Top Layer w0.5: R74.2 OP3.2@74.055,18.655
NetOP4_2: OP4.2 R76.2 | length 3.8
  Top Layer w0.5: R76.2 OP4.2@82.945,18.655
NetPOT1_1: POT1.1 R9.2 | length 12.4
  Top Layer w0.5: R9.2 137.287,54.229 138.049,54.991 POT1.1
NetPOT2_1: POT2.1 R11.2 | length 6.8
  Top Layer w0.5: R11.2@127.127,57.531 131.191,57.531 131.699,57.023 POT2.1
NetPOT2_2: POT2.2 R12.1 | length 4.9
  Top Layer w0.5: R12.1@127.127,50.8 129.159,50.8 130.048,49.911 POT2.2
NetPOT3_1: POT3.1 R15.2 | length 12.4
  Top Layer w0.5: R15.2 137.414,73.025 138.176,73.787 POT3.1
NetPOT4_1: POT4.1 R17.2 | length 6.8
  Top Layer w0.5: R17.2 131.318,76.327 131.826,75.819 POT4.1
NetPOT4_2: POT4.2 R18.1 | length 4.9
  Top Layer w0.5: R18.1 129.286,69.596 130.175,68.707 POT4.2
NetQ1_1: Q1.1 R43.2 R44.1 | length 9.2
  Top Layer w0.5: Q1.1 R44.1 R43.2
NetQ1_3: Q1.3 R45.1 | length 5.8
  Top Layer w0.5: Q1.3 28.26,17.079 29.21,16.129 R45.1
NetQ2_1: Q2.1 R46.2 R47.1 | length 9.2
  Top Layer w0.5: Q2.1 R47.1 R46.2
NetQ2_3: Q2.3 R48.1 | length 5.8
  Top Layer w0.5: Q2.3 14.798,17.206 15.748,16.256 R48.1
NetQ3_1: Q3.1 R49.2 R50.1 | length 9.2
  Top Layer w0.5: Q3.1 R50.1 R49.2
NetQ3_3: Q3.3 R51.1 | length 5.8
  Top Layer w0.5: Q3.3 21.529,17.079 22.479,16.129 R51.1
NetQ4_1: Q4.1 R52.2 R53.1 | length 9.2
  Top Layer w0.5: Q4.1 R53.1 R52.2
NetQ4_3: Q4.3 R54.1 | length 5.8
  Top Layer w0.5: Q4.3 34.991,17.079 35.941,16.129 R54.1
NetQ5_1: Q5.1 R55.2 R56.1 | length 9.2
  Top Layer w0.5: Q5.1 R56.1 R55.2
NetQ5_3: Q5.3 R57.1 | length 5.8
  Top Layer w0.5: Q5.3 41.722,17.079 42.672,16.129 R57.1
NetQ6_1: Q6.1 R58.2 R59.1 | length 9.2
  Top Layer w0.5: Q6.1 R59.1 R58.2
NetQ6_3: Q6.3 R60.1 | length 5.8
  Top Layer w0.5: Q6.3 48.453,17.079 49.403,16.129 R60.1
NetQ7_1: Q7.1 R61.2 R62.1 | length 9.4
  Top Layer w0.5: R61.2 R62.1 96.76,13.731 96.76,19.29 Q7.1
NetQ8_1: Q8.1 R64.2 R65.1 | length 9.3
  Top Layer w0.5: R64.2 R65.1 109.713,13.73 109.713,19.162 Q8.1
NetR2_1: R2.1 R3.2 U1.4 | length 16.5
  Top Layer w1: U1.4 26.211,68.912 26.543,68.58 27.178,68.58 27.813,67.945 ; R3.2 27.813,67.945 ; v1(30.861,70.866) 30.861,68.873 30.568,68.58 28.448,68.58 27.813,67.945
  Bottom Layer w1: R2.1 v1(30.861,70.866)
NetR10_2: R10.2 U5.6 | length 8.7
  Top Layer w0.5: R10.2 156.366,54.581 156.718,54.229 156.718,52.07 157.226,51.562 U5.6
NetR16_2: R16.2 U6.6 | length 8.7
  Top Layer w0.5: R16.2 156.493,73.377 156.845,73.025 156.845,70.866 157.353,70.358 U6.6
NREF: CE7.2 JP2.3 R6.1 R12.2 R18.2 U4.1 | length 80.4
  Top Layer w0.5: JP2.3 123.901,9.728 124.714,10.541 R6.1 U4.1 130.81,13.843 131.445,14.478 131.445,23.368 130.683,24.13 ; R18.2 124.685,66.646 123.825,65.786 123.825,49.022 124.743,48.104 R12.2 130.585,48.104 131.445,47.244 131.445,24.892 130.683,24.13 ; CE7.2 130.683,24.13
NTC1: JP11.1 R67.1 R68.2 | length 12
  Top Layer w0.5: JP11.1 132.459,9.269 133.927,10.737 R68.2 R67.1
NTC2: JP11.4 R69.1 R78.2 | length 11.7
  Top Layer w0.5: R69.1 R78.2 143.637,10.541 144.399,9.779 JP11.4
OP1A: JP7.1 R70.1 | length 9.4
  Top Layer w0.5: JP7.1 57.738,9.478 59.225,10.965 R70.1
OP1K: JP7.2 OP1.1 | length 14.5
  Top Layer w0.5: OP1.1 59.944,18.669 61.718,16.895 JP7.2
OP2A: JP7.3 R72.1 | length 9.7
  Top Layer w0.5: JP7.3 65.698,9.31 68.115,11.727 R72.1
OP2K: JP7.4 OP2.1 | length 14.1
  Top Layer w0.5: OP2.1 68.834,18.669 69.678,17.825 JP7.4
OP3A: JP7.5 R74.1 | length 10.1
  Top Layer w0.5: JP7.5 73.658,8.634 77.005,11.981 R74.1
OP3K: JP7.6 OP3.1 | length 14.6
  Top Layer w0.5: OP3.1 77.978,18.669 78.613,18.034 78.613,9.652 77.638,8.677 JP7.6
OP4A: JP7.7 R76.1 | length 12.1
  Top Layer w0.5: JP7.7 81.618,10.117 82.38,10.879 85.047,10.879 85.895,11.727 R76.1
OP4K: JP7.8 OP4.1 | length 14.9
  Top Layer w0.5: OP4.1 86.741,18.669 87.503,17.907 87.503,11.43 85.598,9.525 JP7.8
PA15: Pd.2 R55.1 | length 75.3
  Top Layer w0.3: 79.756,60.452 79.756,64.162
  Top Layer w0.5: R55.1 v1(39.722,38.735) ; v1(55.753,38.735) v1(55.753,50.8) ; v1(79.756,50.8) 79.756,60.452 ; 79.756,64.162 Pd.2@81.026,65.432
  Bottom Layer w0.5: v1(39.722,38.735) v1(55.753,38.735) ; v1(55.753,50.8) v1(79.756,50.8)
PB3: Pd.7 R58.1 | length 59.1
  Top Layer w0.5: R58.1 46.468,30.72 46.468,40.118 v1(46.482,40.132) ; v1(54.483,40.259) v1(54.483,52.578) ; v1(73.406,52.578) Pd.7
  Bottom Layer w0.5: v1(46.482,40.132) 46.546,40.196 54.42,40.196 v1(54.483,40.259) ; v1(54.483,52.578) v1(73.406,52.578)
PB12: OP3.4 Pc.1 R75.1 | length 31.1
  Top Layer w0.5: R75.1 OP3.4 71.501,29.972 72.517,30.988 83.312,30.988 84.328,32.004 Pc.1
PB13: OP4.4 Pc.2 R77.1 | length 24.9
  Top Layer w0.5: R77.1 OP4.4 80.391,28.448 81.153,29.21 85.852,29.21 86.868,30.226 Pc.2
PB14: Pc.3 Q7.3 R63.2 | length 37.4
  Top Layer w0.3: 85.598,43.18 88.773,43.18
  Top Layer w0.5: Pc.3 85.598,43.18 ; 88.773,43.18 89.662,42.291 89.662,26.416 91.313,24.765 91.313,22.43 92.978,20.765 ; R63.2@92.978,17.54 92.978,20.765 ; Q7.3@97.688,21.654 93.867,21.654 92.978,20.765
PB15: Pc.4 Q8.3 R66.2 | length 51.8
  Top Layer w0.5: R66.2 105.968,20.638 106.857,21.527 ; v1(106.045,45.212) 106.045,22.339 106.857,21.527 ; Q8.3 106.857,21.527
  Bottom Layer w0.5: Pc.4 89.154,44.45 89.916,45.212 v1(106.045,45.212)
PC6: Pc.5 R43.1 | length 74.4
  Top Layer w0.5: R43.1 v1(26.26,34.798) ; v1(59.944,34.798) v1(59.944,46.99)
  Bottom Layer w0.5: v1(26.26,34.798) v1(59.944,34.798) ; v1(59.944,46.99) Pc.5
PC7: Pc.6 R46.1 | length 89.5
  Top Layer w0.5: R46.1 v1(12.798,33.401) ; v1(61.214,33.401) v1(61.214,45.72)
  Bottom Layer w0.3: 81.888,45.72 85.598,45.72
  Bottom Layer w0.5: v1(12.798,33.401) v1(61.214,33.401) ; v1(61.214,45.72) 81.888,45.72 ; 85.598,45.72 Pc.6
PC8: Pc.7 R49.1 | length 83.6
  Top Layer w0.5: R49.1 v1(19.529,37.338) ; v1(57.15,37.338) v1(57.15,49.53)
  Bottom Layer w0.5: v1(19.529,37.338) v1(57.15,37.338) ; v1(57.15,49.53) Pc.7
PC9: Pc.8 R52.1 | length 72
  Top Layer w0.5: R52.1 v1(32.991,36.068) ; v1(58.547,36.068) v1(58.547,48.26)
  Bottom Layer w0.3: 81.788,48.26 85.498,48.26
  Bottom Layer w0.5: v1(32.991,36.068) v1(58.547,36.068) ; v1(58.547,48.26) 81.788,48.26 ; 85.498,48.26 86.768,49.53 Pc.8
PREF: CE6.1 JP2.1 R5.1 R11.1 R17.1 R22.1 R26.1 R30.1 R34.1 R38.1 R42.1 R68.1 R78.1 U3.2 | length 177.3
  Top Layer w0.5: JP2.1 115.941,9.896 116.586,10.541 R5.1 118.237,16.764 118.618,16.383 U3.2 ; CE6.1 121.548,32.14 ; v1(122.555,22.733) 122.555,31.133 121.548,32.14 ; v1(125.349,54.61) 127.156,54.61 R11.1 ; R17.1 123.542,73.377 122.555,72.39 v1(122.555,54.61) 122.555,33.147 121.548,32.14 ; R68.1 v1(138.782,13.716) R78.1 ; v1(146.529,17.526) R22.1 ; v1(154.149,17.526) R26.1 ; v1(161.798,17.526) R30.1 ; v1(169.516,17.526) R34.1 ; v1(177.263,17.526) R38.1 ; v1(184.785,17.526) R42.1
  Bottom Layer w0.5: U3.2 124.206,16.383 ; v1(122.555,22.733) 124.421,22.733 124.714,22.44 124.714,16.891 124.206,16.383 ; v1(122.555,54.61) v1(125.349,54.61) ; v1(184.785,17.526) v1(177.263,17.526) v1(169.516,17.526) v1(161.798,17.526) v1(154.149,17.526) v1(146.529,17.526) 139.319,17.526 138.782,16.989 v1(138.782,13.716) 138.782,11.401 138.303,10.922 125.222,10.922 124.714,11.43 124.714,15.875 124.206,16.383
Q1B: JP8.2 R61.1 | length 15.6
  Top Layer w0.5: R61.1 89.985,10.853 90.424,10.414 97.917,10.414 98.722,9.609 JP8.2
Q1C: JP9.2 R48.2 | length 13.6
  Top Layer w0.5: R48.2 12.798,10.697 13.843,9.652 18.923,9.652 19.808,8.767 JP9.2
Q2B: JP8.3 R64.1 | length 7.7
  Top Layer w0.5: JP8.3 102.702,9.611 102.939,9.848 R64.1
Q2C: JP9.3 R51.2 | length 11.3
  Top Layer w0.5: R51.2 19.529,11.088 19.822,10.795 23.114,10.795 23.788,10.121 JP9.3
Q3C: JP9.4 R45.2 | length 8.2
  Top Layer w0.5: R45.2 26.26,10.951 27.768,9.443 JP9.4
Q4C: JP9.5 R54.2 | length 8.1
  Top Layer w0.5: JP9.5 31.748,9.777 32.991,11.02 R54.2
Q5C: JP9.6 R57.2 | length 10.5
  Top Layer w0.5: JP9.6 35.728,9.566 36.703,10.541 38.862,10.541 39.722,11.401 R57.2
Q6C: JP9.7 R60.2 | length 19
  Top Layer w0.5: JP9.7 39.708,8.593 40.513,9.398 45.847,9.398 46.453,10.004 R60.2 46.453,19.148
REFa: C11.1 POT2.3 U5.5 | length 39.3
  Top Layer w0.5: C11.1 156.083,50.673 157.734,49.022 U5.5
  Bottom Layer w0.5: POT2.3 136.027,52.441 141.097,47.371 144.526,47.371 147.701,50.546 153.543,50.546 155.067,49.022 U5.5
REFb: C18.1 POT4.3 U6.5 | length 39.3
  Top Layer w0.5: C18.1 156.21,69.469 157.861,67.818 U6.5
  Bottom Layer w0.5: POT4.3 136.154,71.237 141.224,66.167 144.653,66.167 147.828,69.342 154.051,69.342 155.575,67.818 U6.5
RG1a: R9.1 U5.1 | length 34.6
  Bottom Layer w0.5: R9.1 137.287,58.928 138.049,59.69 166.624,59.69 167.64,58.674 U5.1
RG1b: R15.1 U6.1 | length 36
  Bottom Layer w0.5: R15.1 137.414,78.232 138.176,78.994 167.259,78.994 167.767,78.486 U6.1
RG2a: POT1.2 POT1.3 U5.8 | length 21.9
  Top Layer w0.5: POT1.2 POT1.3
  Bottom Layer w0.5: POT1.3 152.918,52.461 157.099,56.642 U5.8
RG2b: POT3.2 POT3.3 U6.8 | length 21.9
  Top Layer w0.5: POT3.2 POT3.3
  Bottom Layer w0.5: POT3.3 153.045,71.257 157.226,75.438 U6.8
RS: Pb.7
SD-CLK: JP4.4 Pb.5 | length 61.4
  Top Layer w0.3: 77.216,61.303 77.216,72.136
  Top Layer w0.5: v1(77.216,40.513) 77.216,61.303 ; 77.216,72.136 79.375,74.295 v1(85.404,74.295)
  Bottom Layer w0.5: Pb.5 68.326,39.878 68.961,40.513 v1(77.216,40.513) ; v1(85.404,74.295) JP4.4
SD-DI: JP4.3 Pd.9 | length 34.1
  Top Layer w0.3: 72.136,64.262 72.136,67.972
  Top Layer w0.5: Pd.9 72.136,64.262 ; 72.136,67.972 72.136,74.803 76.581,79.248 86.614,79.248 88.004,80.638 JP4.3
SD-DO: JP4.2 Pd.8 | length 32.1
  Top Layer w0.5: Pd.8 73.406,73.406 77.597,77.597 88.519,77.597 90.604,79.682 JP4.2
SWCLK: Pd.1
SWDIO: Pc.14
USART1-RX: JP6.3 Pd.11 | length 22.2
  Top Layer w0.3: 69.596,64.262 69.596,67.972
  Top Layer w0.5: Pd.11 69.596,64.262 ; 69.596,67.972 69.596,77.851 71.076,79.331 JP6.3
USART1-TX: JP6.1 Pd.10 | length 20.8
  Top Layer w0.5: Pd.10 70.866,76.327 76.276,81.737 JP6.1
V_BAT: Pa.1
VDDA: Pa.13
VSN: JP3a.1 R7.1 | length 20.4
  Top Layer w0.5: R7.1@174.117,47.488 174.117,45.456 174.625,44.948 187.325,44.948 187.833,45.456 JP3a.1
VSP: JP3a.3 R8.1 | length 9.3
  Top Layer w0.5: R8.1@178.562,57.607 JP3a.3
pads on no net: M1.1 M2.1 M3.1 M4.1 M5.1 M6.1 M7.1 OP1.3 OP1.6 OP2.3 OP2.6 OP3.3 OP3.6 OP4.3 OP4.6 Pa.7 Pd.12 U2.1 U2.6 U2.7 U3.3 U4.3

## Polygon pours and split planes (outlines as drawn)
AGND on Bottom Layer "NONET_L-01_P-001" (solid, pour order 5): 104.056,89.38 193.167,89.38 193.167,0.734 114.427,0.734 114.427,25.753 103.971,25.753
GND on Bottom Layer "NONET_L-01_P-001" (solid, pour order 0): 1.143,89.408 102.616,89.408 102.616,24.638 113.538,24.638 113.538,0.762 1.143,0.762
AGND on Top Layer "NONET_L-01_P-001" (solid, pour order 3): 104.098,89.408 193.167,89.408 193.167,0.762 114.427,0.762 114.427,25.781 104.013,25.781
GND on Top Layer "NONET_L-01_P-001" (solid, pour order 2): 1.143,89.408 102.616,89.408 102.616,24.638 113.538,24.638 113.538,0.762 1.143,0.762

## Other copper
Top Layer:
  rectangle net GND: 16.512,80.408 32.512,89.408
  pour cut-out: 1.171,0.226 9.426,0.226 9.426,8.481 1.171,8.481
  pour cut-out: 185.829,0.099 194.084,0.099 194.084,8.354 185.829,8.354
  pour cut-out: 185.575,81.125 193.83,81.125 193.83,89.38 185.575,89.38
  pour cut-out: 1.143,24.653 9.398,24.653 9.398,32.908 1.143,32.908
  pour cut-out: 95.843,24.653 104.098,24.653 104.098,32.908 95.843,32.908
  pour cut-out: 95.843,81.153 104.098,81.153 104.098,89.408 95.843,89.408
  pour cut-out: 1.143,81.153 9.398,81.153 9.398,89.408 1.143,89.408
Bottom Layer:
  rectangle net GND: 16.512,80.408 32.512,89.408
  pour cut-out: 1.171,8.481 1.171,0.226 9.426,0.226 9.426,8.481
  pour cut-out: 185.829,8.354 185.829,0.099 194.084,0.099 194.084,8.354
  pour cut-out: 185.575,89.38 185.575,81.125 193.83,81.125 193.83,89.38
  pour cut-out: 1.143,32.908 1.143,24.653 9.398,24.653 9.398,32.908
  pour cut-out: 95.843,32.908 95.843,24.653 104.098,24.653 104.098,32.908
  pour cut-out: 95.843,89.408 95.843,81.153 104.098,81.153 104.098,89.408
  pour cut-out: 1.143,89.408 1.143,81.153 9.398,81.153 9.398,89.408

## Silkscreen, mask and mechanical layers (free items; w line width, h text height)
Top Overlay:
  lines w0.1: 11.557,26.135 2.794,26.162 2.794,87.757 102.616,87.757 102.616,26.162 50.927,26.162
  text "I2C" at 63.292,88.311 h1.3
  text "USART" at 70.912,88.311 h1.3
  text "SPI" at 85.517,88.311 h1.3
  text "AuxBoard030624" at 124.079,87.376 h1.3
  text "www.nekoorad.com" at 122.347,85.39 h1.5
  text "09191143937" at 124.633,83.231 h1.5
  text "GND" at 80.826,79.575 h1 r90
  text "3V3" at 94.061,79.167 h1.3 r90
  text "GND" at 65.105,77.77 h1.3 r90
  text "GND" at 74.249,77.77 h1.3 r90
  text "PB5-DI" at 88.7,77.543 h1 r90
  text "PA4-CS" at 83.366,76.908 h1 r90
  text "PB4-DO" at 90.732,76.908 h1 r90
  text "ISP" at 185.374,76.5 h1.3 r90
  text "PA5-CLK" at 86.033,76.019 h1 r90
  text "PB7-Rx" at 71.455,75.611 h1.3 r90
  text "PB6-Tx" at 77.043,75.611 h1.3 r90
  text "PB9-SDA" at 62.615,75.434 h1.1 r90
  text "PB8-SCL" at 67.822,75.434 h1.1 r90
  text "12V" at 10.114,73.452 h1.3 r90
  text "PB2" at 192.613,70.785 h1.3 r90
  text "AGND" at 185.12,69.642 h1.3 r90
  text "GND" at 10.114,68.626 h1.3 r90
  text "ISN" at 185.12,65.197 h1.3 r90
  text "12V" at 10.114,64.562 h1.3 r90
  text "GND" at 10.114,59.863 h1.3 r90
  text "VSP" at 185.501,57.323 h1.3 r90
  text "5V" at 10.114,56.434 h1.3 r90
  text "PC5" at 192.613,51.862 h1.3 r90
  text "AGND" at 185.374,51.227 h1.3 r90
  text "VSN" at 185.374,46.909 h1.3 r90
  text "PC15" at 57.958,10.333 h1.3
  text "PB11" at 66.086,10.333 h1.3
  text "PB13" at 81.707,10.333 h1.3
  text "PB12" at 73.833,10.206 h1.3
  text "5V" at 153.878,8.682 h1.3 r90
  text "AGND" at 180.132,8.682 h1.3
  text "5V" at 16.591,8.555 h1.3 r90
  text "PREF" at 113.076,8.555 h1.3
  text "AGND" at 118.156,8.555 h1.3
  text "NREF" at 124.125,8.555 h1.3
  text "PC7" at 20.274,8.428 h1.3 r90
  text "PC8" at 24.338,8.428 h1.3 r90
  text "PC6" at 28.275,8.428 h1.3 r90
  text "PC9" at 32.466,8.428 h1.3 r90
  text "PA15" at 36.403,8.428 h1.1 r90
  text "PB3" at 40.34,8.428 h1.3 r90
  text "PA3" at 131.237,8.428 h1.3
  text "AGND" at 136.19,8.428 h1.3
  text "PB1" at 143.048,8.428 h1.3
  text "PA4" at 157.688,8.428 h1.3 r90
  text "PA6" at 161.752,8.428 h1.3 r90
  text "PA0" at 165.689,8.428 h1.3 r90
  text "PA1" at 169.88,8.428 h1.3 r90
  text "PB0" at 173.817,8.428 h1.3 r90
  text "PC4" at 177.881,8.428 h1.3 r90
  text "5V" at 95.381,8.378 h1.1 r90
  text "PB14" at 99.318,8.378 h1.1 r90
  text "PB15" at 103.255,8.378 h1.1 r90
  text "GND" at 107.446,8.378 h1.1 r90
  text "GND" at 44.404,8.301 h1.3 r90
  text "A" at 57.323,8.301 h1.3
  text "K" at 61.133,8.301 h1.3
  text "A" at 81.072,8.301 h1.3
  text "K" at 84.882,8.301 h1.3
  text "A" at 65.197,8.174 h1.3
  text "K" at 69.007,8.174 h1.3
  text "A" at 73.198,8.174 h1.3
  text "K" at 77.008,8.174 h1.3
  text "ANALOG" at 163.749,1.189 h1.3
  text "NTC" at 137.079,0.935 h1.3
  text "OUTPUT" at 27.224,0.808 h1.3
  text "ISO INPUT" at 68.88,0.808 h1.3
  text "INPUT" at 99.106,0.808 h1.3
Bottom Overlay:
  text "PA4-CS" at 83.62,82.35 h1 r90
  text "PA5-CLK" at 86.16,82.35 h1 r90
  text "PB5-DI" at 88.827,82.35 h1 r90
  text "PB4-DO" at 91.494,82.35 h1 r90
  text "GND" at 80.953,82.223 h1 r90
  text "PB6-Tx" at 77.112,82.164 h1.3 r90
  text "PB9-SDA" at 62.565,82.123 h1.3 r90
  text "PB8-SCL" at 67.772,82.123 h1.3 r90
  text "PB7-Rx" at 71.836,82.123 h1.3 r90
  text "3V3" at 94.061,82.123 h1.3 r90
  text "USART" at 74.376,79.837 h1.3 r90
  text "I2C" at 65.613,78.405 h1.3
  text "PB2" at 185.501,78.151 h1.3
  text "ISP" at 184.993,76.916 h1.3 r90
  text "SPI" at 81.742,74.595 h1.3
  text "12V" at 11.765,73.452 h1.3
  text "AGND" at 185.628,71.674 h1.3
  text "ISN" at 184.739,69.55 h1.3 r90
  text "GND" at 11.511,69.515 h1.3
  text "GND" at 11.511,69.515 h1.3
  text "12V" at 11.765,65.578 h1.3
  text "OFFSETb" at 134.574,63.927 h1.3
  text "GAINb" at 145.369,63.927 h1.3
  text "GND" at 11.511,61.514 h1.3
  text "PC5" at 185.501,60.244 h1.3
  text "VSP" at 185.12,59.263 h1.3 r90
  text "5V" at 11.003,57.577 h1.3
  text "AGND" at 185.628,53.005 h1.3
  text "VSN" at 184.993,51.135 h1.3 r90
  text "OFFSETa" at 134.32,45.258 h1.3
  text "GAINa" at 145.369,45.258 h1.3
  text "OUTPUT" at 33.609,13.889 h1.3
  text "INPUT" at 103.713,13.889 h1.3
  text "ANALOG" at 171.531,13.889 h1.3
  text "ISO INPUT" at 76.154,13.254 h1.3
  text "AGND" at 181.437,12.781 h1.3 r90
  text "PB14" at 99.395,12.654 h1.3 r90
  text "PB15" at 103.332,12.654 h1.3 r90
  text "PA4" at 157.561,12.146 h1.3 r90
  text "PA6" at 161.625,12.146 h1.3 r90
  text "PA0" at 165.562,12.146 h1.3 r90
  text "PA1" at 169.753,12.146 h1.3 r90
  text "PB0" at 173.69,12.146 h1.3 r90
  text "PC4" at 177.754,12.146 h1.3 r90
  text "GND" at 44.404,11.765 h1.3 r90
  text "5V" at 153.751,11.765 h1.3 r90
  text "PC7" at 20.324,11.688 h1.1 r90
  text "PC8" at 24.388,11.688 h1.1 r90
  text "PC6" at 28.325,11.688 h1.1 r90
  text "PC9" at 32.516,11.688 h1.1 r90
  text "PA15" at 36.453,11.688 h1.1 r90
  text "PB3" at 40.39,11.688 h1.1 r90
  text "GND" at 107.523,11.638 h1.3 r90
  text "NTC" at 140.162,11.349 h1.3
  text "5V" at 16.591,11.13 h1.3 r90
  text "5V" at 95.458,10.749 h1.3 r90
  text "PC15" at 61.93,10.46 h1.3
  text "PB13" at 85.679,10.46 h1.3
  text "PB11" at 69.804,10.333 h1.3
  text "PB12" at 77.805,10.333 h1.3
  text "AGND" at 122.509,8.555 h1.3
  text "NREF" at 127.716,8.555 h1.3
  text "PA3" at 134.32,8.555 h1.3
  text "AGND" at 141.051,8.555 h1.3
  text "PB1" at 145.242,8.555 h1.3
  text "A" at 58.374,8.428 h1.3
  text "K" at 62.184,8.428 h1.3
  text "A" at 82.123,8.428 h1.3
  text "K" at 85.933,8.428 h1.3
  text "PREF" at 116.794,8.428 h1.3
  text "A" at 66.248,8.301 h1.3
  text "K" at 70.058,8.301 h1.3
  text "A" at 74.249,8.301 h1.3
  text "K" at 78.059,8.301 h1.3
Mechanical 1:
  the board outline again, w0.254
